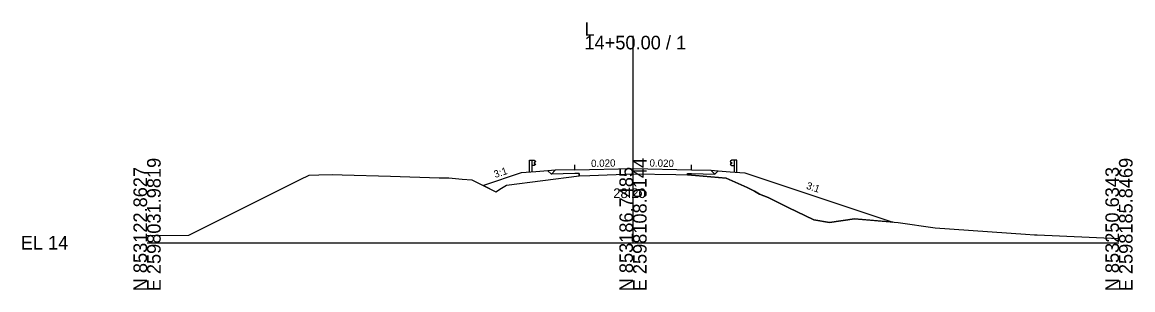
# Model space of a CAD drawing. Extents: x -26 to 1203, y -10 to 9526.
# Drawn here: x -25.7 to 202.8, y 4490.3 to 4545.4 of the extents above; entities that cross this region are included whole.
import ezdxf

# ---------------------------------------------------------------- set-up
doc = ezdxf.new("R2010")
doc.units = 0
for name, color, linetype in [('Exist Cross Section Cell', 7, 'Continuous'), ('Exist XS Center Line Elevation Label', 7, 'Continuous'), ('Exist XS Ground Line', 7, 'Continuous'), ('Prop XS Earthwork Shape', 7, 'Continuous'), ('Prop XS EOT Tick Mark', 7, 'Continuous'), ('Prop XS Finish Grade', 7, 'Continuous'), ('Prop XS Finish Grade Earthwork', 7, 'Continuous'), ('Prop XS Finish Grade Paved Shoulder', 7, 'Continuous'), ('Prop XS Finish Grade Pavement', 7, 'Continuous'), ('Prop XS Guardrail', 7, 'Continuous'), ('Prop XS Pvmt Edge Slope', 7, 'Continuous'), ('Prop XS SE Text', 7, 'Continuous'), ('Prop XS Side Slope Text', 7, 'Continuous'), ('Prop XS Subgrade Earthwork', 7, 'Continuous')]:
    doc.layers.add(name, color=color, linetype=linetype)

msp = doc.modelspace()

# ---------------------------------------------------------------- linework, layer by layer
at = {"layer": 'Exist Cross Section Cell'}
for p, q in [((100, 4500), (100, 4542.62)), ((0, 4500), (100, 4500)), ((100, 4500), (200, 4500))]:
    msp.add_line(p, q, dxfattribs=at)
at = {"layer": 'Exist XS Ground Line'}
for p, q in [((31.51, 4513), (33.35, 4513.92)), ((33.35, 4513.92), (35.35, 4513.98)), ((35.35, 4513.98), (38.12, 4514.06)), ((38.12, 4514.06), (40.12, 4514)), ((40.12, 4514), (50.12, 4513.7)), ((50.12, 4513.7), (60.12, 4513.4)), ((73.97, 4511.84), (88.94, 4513.8)), ((88.94, 4513.8), (91.12, 4513.88)), ((91.12, 4513.88), (100.1, 4514.21)), ((100.1, 4514.21), (108.82, 4514.04)), ((108.82, 4514.04), (111.24, 4513.99)), ((111.24, 4513.99), (112.83, 4513.88)), ((112.83, 4513.88), (119.15, 4513.32)), ((8.59, 4501.54), (31.51, 4513)), ((60.12, 4513.4), (62.12, 4513.34)), ((62.12, 4513.34), (64.86, 4513.12)), ((64.86, 4513.12), (66.86, 4512.96)), ((66.86, 4512.96), (71.78, 4510.5)), ((72.95, 4511.22), (73.97, 4511.84)), ((119.15, 4513.32), (123.51, 4511.36)), ((123.51, 4511.36), (125.03, 4510.64)), ((71.78, 4510.5), (72.95, 4511.22)), ((125.03, 4510.64), (126.01, 4509.98)), ((126.01, 4509.98), (127.79, 4509.31)), ((127.79, 4509.31), (131.93, 4507.23)), ((131.93, 4507.23), (137.18, 4504.72)), ((137.18, 4504.72), (140.41, 4504.19)), ((140.41, 4504.19), (145.55, 4504.89)), ((145.55, 4504.89), (154.54, 4504.14)), ((154.54, 4504.14), (162.17, 4503.09)), ((162.17, 4503.09), (180.73, 4501.76)), ((0, 4501.48), (8.59, 4501.54)), ((180.73, 4501.76), (182.59, 4501.65)), ((182.59, 4501.65), (183.14, 4501.61)), ((183.14, 4501.61), (200, 4500.84))]:
    msp.add_line(p, q, dxfattribs=at)
at = {"layer": 'Prop XS Earthwork Shape'}
for points in [[(76.99, 4514.38), (69.21, 4511.78), (71.78, 4510.5), (72.95, 4511.22), (73.97, 4511.84), (88.94, 4513.8), (88.94, 4514.25), (88, 4514.23), (83.19, 4514.13), (82.5, 4514.82), (80, 4514.62)], [(123.01, 4514.38), (153.47, 4504.23), (145.55, 4504.89), (140.41, 4504.19), (137.18, 4504.72), (131.93, 4507.23), (127.79, 4509.31), (126.01, 4509.98), (125.03, 4510.64), (123.51, 4511.36), (119.15, 4513.32), (112.83, 4513.88), (111.24, 4513.99), (111.24, 4514.24), (112, 4514.23), (116.81, 4514.13), (117.5, 4514.82), (120, 4514.62)]]:
    msp.add_lwpolyline(points, close=True, dxfattribs=at)
at = {"layer": 'Prop XS EOT Tick Mark'}
for p, q in [((88, 4515.02), (88, 4516.02)), ((112, 4515.02), (112, 4516.02))]:
    msp.add_line(p, q, dxfattribs=at)
at = {"layer": 'Prop XS Finish Grade'}
for p, q in [((84, 4514.94), (82.5, 4514.82)), ((116, 4514.94), (117.5, 4514.82))]:
    msp.add_line(p, q, dxfattribs=at)
at = {"layer": 'Prop XS Finish Grade Earthwork'}
for p, q in [((76.99, 4514.38), (69.21, 4511.78)), ((80, 4514.62), (76.99, 4514.38)), ((82.5, 4514.82), (80, 4514.62)), ((117.5, 4514.82), (120, 4514.62)), ((120, 4514.62), (123.01, 4514.38)), ((123.01, 4514.38), (153.47, 4504.23))]:
    msp.add_line(p, q, dxfattribs=at)
at = {"layer": 'Prop XS Finish Grade Paved Shoulder'}
for p, q in [((88, 4515.02), (84, 4514.94)), ((112, 4515.02), (116, 4514.94))]:
    msp.add_line(p, q, dxfattribs=at)
at = {"layer": 'Prop XS Finish Grade Pavement'}
for p, q in [((88, 4515.02), (100, 4515.26)), ((100, 4515.26), (112, 4515.02))]:
    msp.add_line(p, q, dxfattribs=at)
at = {"layer": 'Prop XS Guardrail'}
for p, q in [((78.67, 4517.01), (79.17, 4517.01)), ((78.67, 4514.51), (78.67, 4517.01)), ((79.17, 4517.01), (79.67, 4517.01)), ((79.17, 4517.01), (79.17, 4514.51)), ((79.67, 4515.88), (79.17, 4515.88)), ((79.67, 4517.01), (79.96, 4516.81)), ((79.96, 4516.69), (79.67, 4516.49)), ((79.67, 4516.49), (79.67, 4516.4)), ((79.67, 4516.4), (79.96, 4516.2)), ((79.96, 4516.08), (79.67, 4515.88)), ((79.96, 4516.81), (79.99, 4516.75)), ((79.99, 4516.75), (79.96, 4516.69)), ((79.96, 4516.2), (79.99, 4516.14)), ((79.99, 4516.14), (79.96, 4516.08)), ((120.04, 4516.81), (120.01, 4516.75)), ((120.01, 4516.75), (120.04, 4516.69)), ((120.04, 4516.2), (120.01, 4516.14)), ((120.01, 4516.14), (120.04, 4516.08)), ((120.33, 4517.01), (120.04, 4516.81)), ((120.04, 4516.69), (120.33, 4516.49)), ((120.33, 4516.4), (120.04, 4516.2)), ((120.04, 4516.08), (120.33, 4515.88)), ((120.83, 4517.01), (120.33, 4517.01)), ((120.33, 4516.49), (120.33, 4516.4)), ((120.33, 4515.88), (120.83, 4515.88)), ((121.33, 4517.01), (120.83, 4517.01)), ((120.83, 4517.01), (120.83, 4514.51)), ((121.33, 4514.51), (121.33, 4517.01))]:
    msp.add_line(p, q, dxfattribs=at)
at = {"layer": 'Prop XS Pvmt Edge Slope'}
for p, q in [((84, 4514.94), (83.19, 4514.13)), ((116, 4514.94), (116.81, 4514.13))]:
    msp.add_line(p, q, dxfattribs=at)
at = {"layer": 'Prop XS Subgrade Earthwork'}
for p, q in [((83.19, 4514.13), (82.5, 4514.82)), ((88, 4514.23), (83.19, 4514.13)), ((88.94, 4514.25), (88, 4514.23)), ((88.94, 4514.25), (88.94, 4513.8)), ((111.24, 4514.24), (111.24, 4513.99)), ((111.24, 4514.24), (112, 4514.23)), ((112, 4514.23), (116.81, 4514.13)), ((116.81, 4514.13), (117.5, 4514.82))]:
    msp.add_line(p, q, dxfattribs=at)

# ---------------------------------------------------------------- texts
at = {"layer": 'Exist Cross Section Cell'}
for s, p in [('L', (90, 4542.62)), ('14+50.00 / 1', (90, 4539.82)), ('EL 14', (-26, 4498.6))]:
    msp.add_text(s, height=2.8, dxfattribs=at).set_placement(p)
for s, p in [('E 2598031.9819', (2.8, 4490)), ('E 2598108.9144', (102.8, 4490)), ('E 2598185.8469', (202.8, 4490)), ('N 853122.8627', (0, 4490)), ('N 853186.7485', (100, 4490)), ('N 853250.6343', (200, 4490))]:
    msp.add_text(s, height=2.8, rotation=90, dxfattribs=at).set_placement(p)
at = {"layer": 'Exist XS Center Line Elevation Label'}
msp.add_text('28.20', height=2, dxfattribs=at).set_placement((95.93, 4509.2))
at = {"layer": 'Prop XS SE Text'}
for rotation, p in [(1.1458, (91.38, 4515.59)), (358.8542, (103.38, 4515.69))]:
    msp.add_text('0.020', height=1.5, rotation=rotation, dxfattribs=at).set_placement(p)
at = {"layer": 'Prop XS Side Slope Text'}
for rotation, p in [(18.4349, (71.64, 4513.32)), (341.5651, (135.52, 4511.16))]:
    msp.add_text('3:1', height=1.5, rotation=rotation, dxfattribs=at).set_placement(p)

doc.saveas('drawing.dxf')
